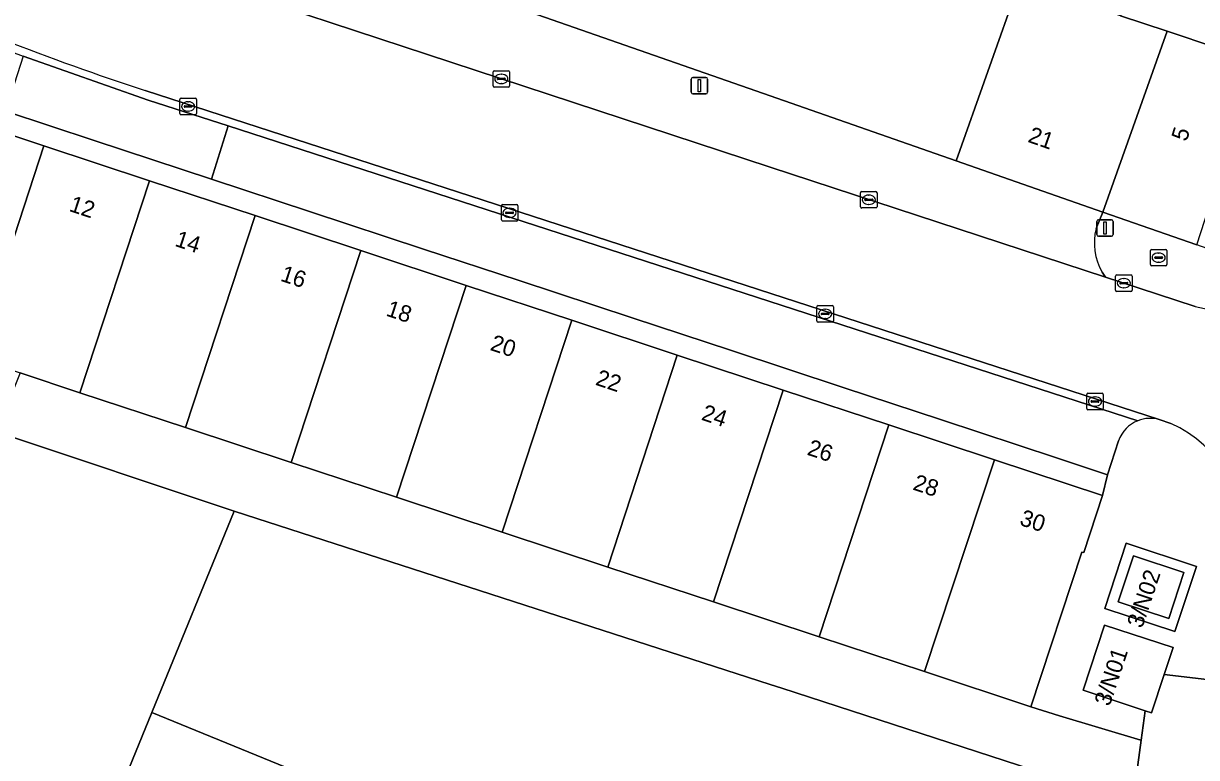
# Model space of a CAD drawing. Extents: x 160554 to 161248, y 385329 to 386506.
# Drawn here: x 160954.7 to 161025.9, y 385787.9 to 385832.5 of the extents above; entities that cross this region are included whole.
import ezdxf

# ---------------------------------------------------------------- set-up
doc = ezdxf.new("R2010")
doc.units = 0
for name, color, linetype in [('IMGEO_Brandkraan', 7, 'Continuous'), ('IMGEO_Erf', 7, 'Continuous'), ('IMGEO_Kolk', 7, 'Continuous'), ('IMGEO_Lichtmast', 7, 'Continuous'), ('IMGEO_Pand', 7, 'Continuous'), ('IMGEO_Pand_nummerreeks', 7, 'Continuous'), ('IMGEO_Parkeervlak_open', 7, 'Continuous'), ('IMGEO_Rijbaan_lokaal_gesloten', 7, 'Continuous'), ('IMGEO_Rijbaan_lokaal_open', 7, 'Continuous'), ('IMGEO_Voetpad_open', 7, 'Continuous')]:
    doc.layers.add(name, color=color, linetype=linetype)

msp = doc.modelspace()

# ---------------------------------------------------------------- linework, layer by layer
at = {"layer": 'IMGEO_Brandkraan'}
for p, q in [((161023.096, 385817.872), (161023.096, 385818.724)), ((161023.171, 385818.798), (161024.023, 385818.798)), ((161023.355, 385818.292), (161023.355, 385818.304)), ((161023.398, 385818.341), (161023.796, 385818.341)), ((161023.584, 385818.578), (161023.609, 385818.578)), ((161023.839, 385818.304), (161023.839, 385818.292)), ((161024.097, 385818.724), (161024.097, 385817.872)), ((161024.023, 385817.798), (161023.171, 385817.798)), ((161023.793, 385818.255), (161023.395, 385818.255)), ((161023.607, 385818.018), (161023.582, 385818.018))]:
    msp.add_line(p, q, dxfattribs=at)
for points in [[(161023.096, 385817.872), (161023.096, 385818.724)], [(161023.171, 385818.798), (161024.023, 385818.798)], [(161024.097, 385818.724), (161024.097, 385817.872)], [(161024.023, 385817.798), (161023.171, 385817.798)]]:
    msp.add_lwpolyline(points, dxfattribs=at)
for centre, radius, start, end in [((161023.173, 385818.722), 0.0765, 91.55205, 178.44795), ((161023.173, 385818.722), 0.0765, 91.55205, 178.44795), ((161023.395, 385818.301), 0.0403, 85.87752, 175.75265), ((161023.392, 385818.291), 0.0366, 178.93798, 274.71019), ((161023.796, 385818.298), 0.043, 264.86636, 352.45326), ((161023.8, 385818.303), 0.0386, 1.73085, 96.63898), ((161024.021, 385818.722), 0.0765, 1.55205, 88.44795), ((161024.021, 385818.722), 0.0765, 1.55205, 88.44795), ((161023.173, 385817.874), 0.0765, 181.55205, 268.44795), ((161023.173, 385817.874), 0.0765, 181.55205, 268.44795), ((161024.021, 385817.874), 0.0765, 271.55205, 358.44795), ((161024.021, 385817.874), 0.0765, 271.55205, 358.44795)]:
    msp.add_arc(centre, radius, start, end, dxfattribs=at)
for centre, major_axis, ratio, start_param, end_param in [((161023.583, 385818.298), (-0.387, 0.002), 0.722429, 4.712389, 7.853982), ((161023.608, 385818.298), (-0.39, 0.002), 0.717154, 1.570796, 4.712389)]:
    msp.add_ellipse(centre, major_axis=major_axis, ratio=ratio, start_param=start_param, end_param=end_param, dxfattribs=at)
at = {"layer": 'IMGEO_Erf'}
msp.add_lwpolyline([(161000.723, 385792.149), (161000, 385792.384), (160967.473, 385802.912), (160962.472, 385790.676), (160994.492, 385777.59), (160990.901, 385768.804), (160991.347, 385768.622), (161000, 385765.086), (161004.935, 385763.068), (161009.112, 385773.288), (161020.238, 385768.73), (161021.018, 385775.893), (161021.509, 385780.411), (161021.746, 385782.591), (161022.037, 385785.258), (161015.078, 385787.473)], close=True, dxfattribs=at)
at = {"layer": 'IMGEO_Kolk'}
for p, q in [((160983.185, 385828.725), (160983.185, 385829.577)), ((160983.26, 385829.651), (160984.112, 385829.651)), ((160983.444, 385829.145), (160983.444, 385829.157)), ((160983.882, 385829.108), (160983.484, 385829.108)), ((160983.487, 385829.194), (160983.885, 385829.194)), ((160983.673, 385829.431), (160983.698, 385829.431)), ((160983.928, 385829.157), (160983.928, 385829.145)), ((160984.186, 385829.577), (160984.186, 385828.725)), ((160984.112, 385828.651), (160983.26, 385828.651)), ((160983.696, 385828.871), (160983.671, 385828.871)), ((160964.171, 385827.054), (160964.171, 385827.906)), ((160964.246, 385827.98), (160965.098, 385827.98)), ((160964.659, 385827.76), (160964.684, 385827.76)), ((160965.172, 385827.906), (160965.172, 385827.054)), ((160965.098, 385826.98), (160964.246, 385826.98)), ((160964.43, 385827.474), (160964.43, 385827.486)), ((160964.868, 385827.437), (160964.47, 385827.437)), ((160964.473, 385827.523), (160964.871, 385827.523)), ((160964.682, 385827.2), (160964.657, 385827.2)), ((160964.914, 385827.486), (160964.914, 385827.474)), ((161005.496, 385821.387), (161005.496, 385822.239)), ((161005.571, 385822.313), (161006.423, 385822.313)), ((161005.798, 385821.856), (161006.196, 385821.856)), ((161005.984, 385822.093), (161006.009, 385822.093)), ((161006.497, 385822.239), (161006.497, 385821.387)), ((160983.688, 385820.596), (160983.688, 385821.448)), ((160983.763, 385821.522), (160984.615, 385821.522)), ((160984.176, 385821.302), (160984.201, 385821.302)), ((160984.689, 385821.448), (160984.689, 385820.596)), ((161006.423, 385821.313), (161005.571, 385821.313)), ((161005.755, 385821.807), (161005.755, 385821.819)), ((161006.193, 385821.77), (161005.795, 385821.77)), ((161006.007, 385821.533), (161005.982, 385821.533)), ((161006.239, 385821.819), (161006.239, 385821.807)), ((160984.615, 385820.522), (160983.763, 385820.522)), ((160983.947, 385821.016), (160983.947, 385821.028)), ((160984.385, 385820.979), (160983.987, 385820.979)), ((160983.99, 385821.065), (160984.388, 385821.065)), ((160984.199, 385820.742), (160984.174, 385820.742)), ((160984.431, 385821.028), (160984.431, 385821.016)), ((161020.982, 385816.32), (161020.982, 385817.172)), ((161021.057, 385817.246), (161021.909, 385817.246)), ((161021.47, 385817.026), (161021.495, 385817.026)), ((161021.983, 385817.172), (161021.983, 385816.32)), ((161021.909, 385816.246), (161021.057, 385816.246)), ((161021.241, 385816.74), (161021.241, 385816.752)), ((161021.679, 385816.703), (161021.281, 385816.703)), ((161021.284, 385816.789), (161021.682, 385816.789)), ((161021.493, 385816.466), (161021.468, 385816.466)), ((161021.725, 385816.752), (161021.725, 385816.74)), ((161002.85, 385814.457), (161002.85, 385815.309)), ((161002.925, 385815.383), (161003.777, 385815.383)), ((161003.109, 385814.877), (161003.109, 385814.889)), ((161003.547, 385814.84), (161003.149, 385814.84)), ((161003.152, 385814.926), (161003.55, 385814.926)), ((161003.338, 385815.163), (161003.363, 385815.163)), ((161003.593, 385814.889), (161003.593, 385814.877)), ((161003.851, 385815.309), (161003.851, 385814.457)), ((161003.777, 385814.383), (161002.925, 385814.383)), ((161003.361, 385814.603), (161003.336, 385814.603)), ((161019.23, 385809.139), (161019.23, 385809.991)), ((161019.305, 385810.065), (161020.157, 385810.065)), ((161019.718, 385809.845), (161019.743, 385809.845)), ((161020.231, 385809.991), (161020.231, 385809.139)), ((161020.157, 385809.065), (161019.305, 385809.065)), ((161019.489, 385809.559), (161019.489, 385809.571)), ((161019.927, 385809.522), (161019.529, 385809.522)), ((161019.532, 385809.608), (161019.93, 385809.608)), ((161019.741, 385809.285), (161019.716, 385809.285)), ((161019.973, 385809.571), (161019.973, 385809.559))]:
    msp.add_line(p, q, dxfattribs=at)
for points in [[(160983.185, 385828.725), (160983.185, 385829.577)], [(160983.26, 385829.651), (160984.112, 385829.651)], [(160984.186, 385829.577), (160984.186, 385828.725)], [(160984.112, 385828.651), (160983.26, 385828.651)], [(160964.171, 385827.054), (160964.171, 385827.906)], [(160964.246, 385827.98), (160965.098, 385827.98)], [(160965.172, 385827.906), (160965.172, 385827.054)], [(160965.098, 385826.98), (160964.246, 385826.98)], [(161005.496, 385821.387), (161005.496, 385822.239)], [(161005.571, 385822.313), (161006.423, 385822.313)], [(161006.497, 385822.239), (161006.497, 385821.387)], [(160983.688, 385820.596), (160983.688, 385821.448)], [(160983.763, 385821.522), (160984.615, 385821.522)], [(160984.689, 385821.448), (160984.689, 385820.596)], [(161006.423, 385821.313), (161005.571, 385821.313)], [(160984.615, 385820.522), (160983.763, 385820.522)], [(161020.982, 385816.32), (161020.982, 385817.172)], [(161021.057, 385817.246), (161021.909, 385817.246)], [(161021.983, 385817.172), (161021.983, 385816.32)], [(161021.909, 385816.246), (161021.057, 385816.246)], [(161002.85, 385814.457), (161002.85, 385815.309)], [(161002.925, 385815.383), (161003.777, 385815.383)], [(161003.851, 385815.309), (161003.851, 385814.457)], [(161003.777, 385814.383), (161002.925, 385814.383)], [(161019.23, 385809.139), (161019.23, 385809.991)], [(161019.305, 385810.065), (161020.157, 385810.065)], [(161020.231, 385809.991), (161020.231, 385809.139)], [(161020.157, 385809.065), (161019.305, 385809.065)]]:
    msp.add_lwpolyline(points, dxfattribs=at)
for centre, radius, start, end in [((160983.262, 385829.575), 0.0765, 91.55205, 178.44795), ((160983.262, 385829.575), 0.0765, 91.55205, 178.44795), ((160983.484, 385829.154), 0.0403, 85.87752, 175.75265), ((160983.481, 385829.144), 0.0366, 178.93798, 274.71019), ((160983.885, 385829.151), 0.043, 264.86636, 352.45326), ((160983.889, 385829.156), 0.0386, 1.73085, 96.63898), ((160984.11, 385829.575), 0.0765, 1.55205, 88.44795), ((160984.11, 385829.575), 0.0765, 1.55205, 88.44795), ((160983.262, 385828.727), 0.0765, 181.55205, 268.44795), ((160983.262, 385828.727), 0.0765, 181.55205, 268.44795), ((160984.11, 385828.727), 0.0765, 271.55205, 358.44795), ((160984.11, 385828.727), 0.0765, 271.55205, 358.44795), ((160964.248, 385827.904), 0.0765, 91.55205, 178.44795), ((160964.248, 385827.904), 0.0765, 91.55205, 178.44795), ((160965.096, 385827.904), 0.0765, 1.55205, 88.44795), ((160965.096, 385827.904), 0.0765, 1.55205, 88.44795), ((160964.248, 385827.056), 0.0765, 181.55205, 268.44795), ((160964.248, 385827.056), 0.0765, 181.55205, 268.44795), ((160964.47, 385827.483), 0.0403, 85.87752, 175.75265), ((160964.467, 385827.473), 0.0366, 178.93798, 274.71019), ((160964.871, 385827.48), 0.043, 264.86636, 352.45326), ((160964.875, 385827.485), 0.0386, 1.73085, 96.63898), ((160965.096, 385827.056), 0.0765, 271.55205, 358.44795), ((160965.096, 385827.056), 0.0765, 271.55205, 358.44795), ((161005.573, 385822.237), 0.0765, 91.55205, 178.44795), ((161005.573, 385822.237), 0.0765, 91.55205, 178.44795), ((161005.795, 385821.816), 0.0403, 85.87752, 175.75265), ((161006.2, 385821.818), 0.0386, 1.73085, 96.63898), ((161006.421, 385822.237), 0.0765, 1.55205, 88.44795), ((161006.421, 385822.237), 0.0765, 1.55205, 88.44795), ((160983.765, 385821.446), 0.0765, 91.55205, 178.44795), ((160983.765, 385821.446), 0.0765, 91.55205, 178.44795), ((160984.613, 385821.446), 0.0765, 1.55205, 88.44795), ((160984.613, 385821.446), 0.0765, 1.55205, 88.44795), ((161005.573, 385821.389), 0.0765, 181.55205, 268.44795), ((161005.573, 385821.389), 0.0765, 181.55205, 268.44795), ((161005.792, 385821.806), 0.0366, 178.93798, 274.71019), ((161006.196, 385821.813), 0.043, 264.86636, 352.45326), ((161006.421, 385821.389), 0.0765, 271.55205, 358.44795), ((161006.421, 385821.389), 0.0765, 271.55205, 358.44795), ((160983.765, 385820.598), 0.0765, 181.55205, 268.44795), ((160983.765, 385820.598), 0.0765, 181.55205, 268.44795), ((160983.987, 385821.025), 0.0403, 85.87752, 175.75265), ((160983.984, 385821.015), 0.0366, 178.93798, 274.71019), ((160984.388, 385821.022), 0.043, 264.86636, 352.45326), ((160984.392, 385821.027), 0.0386, 1.73085, 96.63898), ((160984.613, 385820.598), 0.0765, 271.55205, 358.44795), ((160984.613, 385820.598), 0.0765, 271.55205, 358.44795), ((161021.059, 385817.17), 0.0765, 91.55205, 178.44795), ((161021.059, 385817.17), 0.0765, 91.55205, 178.44795), ((161021.907, 385817.17), 0.0765, 1.55205, 88.44795), ((161021.907, 385817.17), 0.0765, 1.55205, 88.44795), ((161021.059, 385816.322), 0.0765, 181.55205, 268.44795), ((161021.059, 385816.322), 0.0765, 181.55205, 268.44795), ((161021.281, 385816.749), 0.0403, 85.87752, 175.75265), ((161021.278, 385816.739), 0.0366, 178.93798, 274.71019), ((161021.682, 385816.746), 0.043, 264.86636, 352.45326), ((161021.686, 385816.751), 0.0386, 1.73085, 96.63898), ((161021.907, 385816.322), 0.0765, 271.55205, 358.44795), ((161021.907, 385816.322), 0.0765, 271.55205, 358.44795), ((161002.927, 385815.307), 0.0765, 91.55205, 178.44795), ((161002.927, 385815.307), 0.0765, 91.55205, 178.44795), ((161003.149, 385814.886), 0.0403, 85.87752, 175.75265), ((161003.146, 385814.876), 0.0366, 178.93798, 274.71019), ((161003.55, 385814.883), 0.043, 264.86636, 352.45326), ((161003.554, 385814.888), 0.0386, 1.73085, 96.63898), ((161003.775, 385815.307), 0.0765, 1.55205, 88.44795), ((161003.775, 385815.307), 0.0765, 1.55205, 88.44795), ((161002.927, 385814.459), 0.0765, 181.55205, 268.44795), ((161002.927, 385814.459), 0.0765, 181.55205, 268.44795), ((161003.775, 385814.459), 0.0765, 271.55205, 358.44795), ((161003.775, 385814.459), 0.0765, 271.55205, 358.44795), ((161019.307, 385809.989), 0.0765, 91.55205, 178.44795), ((161019.307, 385809.989), 0.0765, 91.55205, 178.44795), ((161020.155, 385809.989), 0.0765, 1.55205, 88.44795), ((161020.155, 385809.989), 0.0765, 1.55205, 88.44795), ((161019.307, 385809.141), 0.0765, 181.55205, 268.44795), ((161019.307, 385809.141), 0.0765, 181.55205, 268.44795), ((161019.529, 385809.568), 0.0403, 85.87752, 175.75265), ((161019.526, 385809.558), 0.0366, 178.93798, 274.71019), ((161019.93, 385809.565), 0.043, 264.86636, 352.45326), ((161019.934, 385809.57), 0.0386, 1.73085, 96.63898), ((161020.155, 385809.141), 0.0765, 271.55205, 358.44795), ((161020.155, 385809.141), 0.0765, 271.55205, 358.44795)]:
    msp.add_arc(centre, radius, start, end, dxfattribs=at)
for centre, major_axis, ratio, start_param, end_param in [((160983.672, 385829.151), (-0.387, 0.002), 0.722429, 4.712389, 7.853982), ((160983.697, 385829.151), (-0.39, 0.002), 0.717154, 1.570796, 4.712389), ((160964.658, 385827.48), (-0.387, 0.002), 0.722429, 4.712389, 7.853982), ((160964.683, 385827.48), (-0.39, 0.002), 0.717154, 1.570796, 4.712389), ((161005.983, 385821.813), (-0.387, 0.002), 0.722429, 4.712389, 7.853982), ((161006.008, 385821.813), (-0.39, 0.002), 0.717154, 1.570796, 4.712389), ((160984.175, 385821.022), (-0.387, 0.002), 0.722429, 4.712389, 7.853982), ((160984.2, 385821.022), (-0.39, 0.002), 0.717154, 1.570796, 4.712389), ((161021.469, 385816.746), (-0.387, 0.002), 0.722429, 4.712389, 7.853982), ((161021.494, 385816.746), (-0.39, 0.002), 0.717154, 1.570796, 4.712389), ((161003.337, 385814.883), (-0.387, 0.002), 0.722429, 4.712389, 7.853982), ((161003.362, 385814.883), (-0.39, 0.002), 0.717154, 1.570796, 4.712389), ((161019.717, 385809.565), (-0.387, 0.002), 0.722429, 4.712389, 7.853982), ((161019.742, 385809.565), (-0.39, 0.002), 0.717154, 1.570796, 4.712389)]:
    msp.add_ellipse(centre, major_axis=major_axis, ratio=ratio, start_param=start_param, end_param=end_param, dxfattribs=at)
at = {"layer": 'IMGEO_Lichtmast'}
for p, q in [((160995.216, 385828.337), (160995.216, 385829.137)), ((160995.216, 385829.137), (160995.216, 385828.337)), ((160995.316, 385829.237), (160996.106, 385829.237)), ((160996.106, 385829.237), (160995.316, 385829.237)), ((160996.206, 385829.137), (160996.206, 385828.337)), ((160996.206, 385828.337), (160996.206, 385829.137)), ((160996.106, 385828.237), (160995.316, 385828.237)), ((160995.316, 385828.237), (160996.106, 385828.237)), ((161019.84, 385819.7), (161019.84, 385820.5)), ((161019.84, 385820.5), (161019.84, 385819.7)), ((161019.94, 385820.6), (161020.73, 385820.6)), ((161020.73, 385820.6), (161019.94, 385820.6)), ((161020.83, 385820.5), (161020.83, 385819.7)), ((161020.83, 385819.7), (161020.83, 385820.5)), ((161020.73, 385819.6), (161019.94, 385819.6)), ((161019.94, 385819.6), (161020.73, 385819.6))]:
    msp.add_line(p, q, dxfattribs=at)
for points in [[(160995.636, 385829.112), (160995.786, 385829.112), (160995.786, 385828.362), (160995.636, 385828.362), (160995.636, 385829.112)], [(161020.26, 385820.475), (161020.41, 385820.475), (161020.41, 385819.725), (161020.26, 385819.725), (161020.26, 385820.475)]]:
    msp.add_lwpolyline(points, dxfattribs=at)
for centre, start, end in [((160995.316, 385829.137), 90, 180), ((160995.316, 385829.137), 90, 180), ((160996.106, 385829.137), 0, 90), ((160996.106, 385829.137), 360, 90), ((160995.316, 385828.337), 180, 270), ((160995.316, 385828.337), 180, 270), ((160996.106, 385828.337), 270, 0), ((160996.106, 385828.337), 270, 0), ((161019.94, 385820.5), 90, 180), ((161019.94, 385820.5), 90, 180), ((161020.73, 385820.5), 0, 90), ((161020.73, 385820.5), 360, 90), ((161019.94, 385819.7), 180, 270), ((161019.94, 385819.7), 180, 270), ((161020.73, 385819.7), 270, 0), ((161020.73, 385819.7), 270, 0)]:
    msp.add_arc(centre, 0.1, start, end, dxfattribs=at)
at = {"layer": 'IMGEO_Pand'}
for points in [[(160944.538, 385862.952), (160944.826, 385863.775), (160944.877, 385863.921), (160939.825, 385865.879), (160939.428, 385864.745), (160937.341, 385865.474), (160935.807, 385861.085), (160935.65, 385860.635), (160934.169, 385856.4), (160932.519, 385851.68), (160932.947, 385851.53), (161000, 385828.117), (161011.302, 385824.17), (161015.15, 385835.043), (161016.153, 385837.917), (161000, 385843.564)], [(161028.571, 385835.139), (161022.748, 385837.175), (161021.286, 385832.99), (161024.105, 385832.047), (161027.138, 385831.032)], [(161020.216, 385821.058), (161024.105, 385832.047), (161021.286, 385832.99), (161015.15, 385835.043), (161011.302, 385824.17)], [(161025.905, 385819.071), (161028.066, 385825.689), (161029.548, 385830.225), (161027.138, 385831.032), (161024.105, 385832.047), (161020.216, 385821.058)], [(160955.918, 385825.083), (160949.248, 385827.289), (160945.011, 385814.496), (160951.691, 385812.236)], [(160951.691, 385812.236), (160954.47, 385811.296), (160958.1, 385810.097), (160962.325, 385822.967), (160955.918, 385825.083)], [(160968.736, 385820.849), (160962.325, 385822.967), (160958.1, 385810.097), (160964.504, 385807.982)], [(160964.504, 385807.982), (160970.917, 385805.864), (160975.148, 385818.731), (160968.736, 385820.849)], [(160970.917, 385805.864), (160977.324, 385803.748), (160981.554, 385816.616), (160975.148, 385818.731)], [(160987.964, 385814.499), (160981.554, 385816.616), (160977.324, 385803.748), (160983.732, 385801.632)], [(160983.732, 385801.632), (160990.148, 385799.513), (160994.368, 385812.384), (160987.964, 385814.499)], [(161000.803, 385810.259), (160994.368, 385812.384), (160990.148, 385799.513), (160996.561, 385797.395)], [(160996.561, 385797.395), (161002.975, 385795.277), (161007.217, 385808.14), (161000.803, 385810.259)], [(160962.472, 385790.676), (160967.473, 385802.912), (160953.012, 385807.728), (160949.553, 385799.263), (160931.297, 385754.531), (160932.023, 385754.224), (160932.167, 385754.781), (160932.365, 385755.361), (160941.389, 385751.626), (160946.183, 385753.169), (160946.649, 385752.951), (160945.566, 385750), (160945.353, 385749.419), (160944.823, 385749.599), (160944.596, 385749.072), (160945.129, 385748.857), (160945.33, 385748.776), (160945.831, 385750)], [(161013.631, 385806.022), (161007.217, 385808.14), (161002.975, 385795.277), (161009.389, 385793.158)], [(161020.182, 385803.858), (161013.631, 385806.022), (161009.389, 385793.158), (161015.834, 385791.03), (161018.94, 385800.419), (161019.044, 385800.392)], [(161025.133, 385799.18), (161022.062, 385800.193), (161021.141, 385797.399), (161024.212, 385796.387)], [(161023.931, 385792.984), (161024.47, 385794.616), (161020.314, 385795.986), (161019.011, 385792.034), (161022.786, 385790.789), (161023.166, 385790.664)], [(160948.328, 385747.565), (160959.223, 385743.167), (160965.928, 385740.46), (160976.007, 385736.39), (160977.537, 385735.773), (160977.766, 385735.68), (160983.669, 385750), (160991.347, 385768.622), (160990.901, 385768.804), (160994.492, 385777.59), (160962.472, 385790.676), (160945.831, 385750), (160945.33, 385748.776)]]:
    msp.add_lwpolyline(points, close=True, dxfattribs=at)
at = {"layer": 'IMGEO_Parkeervlak_open'}
for points in [[(161019.795, 385820.06), (161020.216, 385821.058), (161011.302, 385824.17), (161000, 385828.117), (160932.947, 385851.53)], [(160963.127, 385835.929), (160982.091, 385829.674), (161000, 385823.784), (161020.378, 385817.108), (161020.16, 385817.413)], [(161028.597, 385818.115), (161025.905, 385819.071), (161020.216, 385821.058), (161019.795, 385820.06)], [(161020.16, 385817.413), (161020.378, 385817.108), (161021.308, 385816.803), (161025.817, 385815.326)]]:
    msp.add_lwpolyline(points, dxfattribs=at)
for centre, radius, start, end in [((161023.343, 385819.201), 3.651, 166.385, 209.31723), ((161023.343, 385819.201), 3.651, 166.385, 209.31723), ((161027.278, 385821.286), 6.136, 256.22773, 340.1079)]:
    msp.add_arc(centre, radius, start, end, dxfattribs=at)
at = {"layer": 'IMGEO_Rijbaan_lokaal_gesloten'}
for points in [[(161021.308, 385816.803), (161020.378, 385817.108), (161000, 385823.784), (160982.091, 385829.674), (160963.127, 385835.929)], [(160962.067, 385828.449), (161023.625, 385808.465), (161024.336, 385808.234)], [(161025.817, 385815.326), (161021.308, 385816.803)]]:
    msp.add_lwpolyline(points, dxfattribs=at)
for centre, radius, start, end in [((161011.773, 385980.572), 160.038, 248.60785, 251.90538), ((161027.278, 385821.286), 6.136, 256.22773, 340.1079), ((161021.231, 385801.325), 7.574, 353.66767, 65.79818)]:
    msp.add_arc(centre, radius, start, end, dxfattribs=at)
at = {"layer": 'IMGEO_Rijbaan_lokaal_open'}
for points in [[(160953.399, 385831.56), (160943.719, 385835.176), (160936.154, 385838.328), (160900.444, 385853.054), (160893.378, 385856.039), (160893.195, 385855.607), (160893.326, 385855.547), (160893.484, 385855.474), (160893.513, 385855.461), (160893.952, 385855.26), (160943.83, 385834.567), (160947.696, 385833.124), (160950.55, 385832.059), (160954.657, 385830.526), (160962.252, 385827.866), (160967.092, 385826.298), (161022.331, 385808.398)], [(161023.625, 385808.465), (160962.067, 385828.449)]]:
    msp.add_lwpolyline(points, dxfattribs=at)
for centre, radius, start, end in [((161011.773, 385980.572), 160.038, 248.60785, 251.90538), ((161023.077, 385806.52), 2.021, 74.26485, 111.66312)]:
    msp.add_arc(centre, radius, start, end, dxfattribs=at)
at = {"layer": 'IMGEO_Voetpad_open'}
for points in [[(160962.252, 385827.866), (160954.657, 385830.526), (160953.585, 385827.196), (160958.971, 385825.42), (160966.095, 385823.068), (160967.092, 385826.298)], [(161009.389, 385793.158), (161002.975, 385795.277), (160996.561, 385797.395), (160990.148, 385799.513), (160983.732, 385801.632), (160977.324, 385803.748), (160970.917, 385805.864), (160964.504, 385807.982), (160958.1, 385810.097), (160954.47, 385811.296), (160953.012, 385807.728), (160967.473, 385802.912), (161000, 385792.384), (161000.723, 385792.149), (161015.078, 385787.473), (161022.037, 385785.258), (161022.544, 385789.002), (161022.519, 385789.006), (161017.577, 385790.485), (161015.834, 385791.03)], [(161025.889, 385799.552), (161021.626, 385800.957), (161020.322, 385797), (161024.583, 385795.594)], [(161024.583, 385795.594), (161020.322, 385797), (161021.626, 385800.957), (161025.889, 385799.552)], [(161024.212, 385796.387), (161021.141, 385797.399), (161022.062, 385800.193), (161025.133, 385799.18)]]:
    msp.add_lwpolyline(points, close=True, dxfattribs=at)
for points in [[(160949.248, 385827.289), (160955.918, 385825.083), (160962.325, 385822.967), (160968.736, 385820.849), (160975.148, 385818.731), (160981.554, 385816.616), (160987.964, 385814.499), (160994.368, 385812.384), (161000.803, 385810.259), (161007.217, 385808.14), (161013.631, 385806.022), (161020.182, 385803.858), (161020.495, 385805.112), (161017.392, 385806.137), (161010.411, 385808.441), (161004.445, 385810.41), (160997.653, 385812.653), (160991.634, 385814.639), (160984.766, 385816.906), (160978.962, 385818.822), (160972.108, 385821.084), (160966.095, 385823.068), (160958.971, 385825.42), (160953.585, 385827.196)], [(160967.092, 385826.298), (160966.095, 385823.068)], [(161022.331, 385808.398), (160967.092, 385826.298)], [(160966.095, 385823.068), (160972.108, 385821.084)], [(160972.108, 385821.084), (160978.962, 385818.822)], [(160978.962, 385818.822), (160984.766, 385816.906)], [(160984.766, 385816.906), (160991.634, 385814.639)], [(160991.634, 385814.639), (160997.653, 385812.653)], [(160997.653, 385812.653), (161004.445, 385810.41)], [(161004.445, 385810.41), (161010.411, 385808.441)], [(161010.411, 385808.441), (161017.392, 385806.137)], [(161024.336, 385808.234), (161023.625, 385808.465)], [(161021.167, 385807.181), (161020.495, 385805.112), (161020.182, 385803.858), (161019.044, 385800.392), (161018.94, 385800.419), (161015.834, 385791.03), (161017.577, 385790.485), (161022.519, 385789.006), (161022.544, 385789.002), (161022.786, 385790.789), (161019.011, 385792.034), (161020.314, 385795.986), (161024.47, 385794.616), (161023.931, 385792.984), (161027.908, 385792.526), (161028.163, 385795.052), (161028.759, 385800.49)], [(161020.495, 385805.112), (161021.167, 385807.181)], [(161017.392, 385806.137), (161020.495, 385805.112)], [(161027.908, 385792.526), (161023.931, 385792.984), (161023.166, 385790.664), (161022.786, 385790.789), (161022.544, 385789.002), (161022.037, 385785.258), (161021.746, 385782.591), (161026.321, 385782.026)]]:
    msp.add_lwpolyline(points, dxfattribs=at)
for centre, radius, start, end in [((161023.078, 385806.518), 2.023, 111.6802, 160.87013), ((161023.078, 385806.518), 2.023, 111.6802, 160.87013), ((161023.077, 385806.52), 2.021, 74.26485, 111.66312), ((161021.231, 385801.325), 7.574, 353.66767, 65.79818)]:
    msp.add_arc(centre, radius, start, end, dxfattribs=at)

# ---------------------------------------------------------------- texts
at = {"layer": 'IMGEO_Pand_nummerreeks'}
for s, rotation, p in [('21', 340.7552, (161015.604, 385825.337)), ('5', 71.91323, (161025.29, 385825.306)), ('12', 341.72327, (160957.392, 385821.142)), ('14', 341.72327, (160963.807, 385819.023)), ('16', 341.72327, (160970.218, 385816.905)), ('18', 341.72327, (160976.63, 385814.788)), ('20', 341.72327, (160982.952, 385812.7)), ('22', 341.72327, (160989.349, 385810.587)), ('24', 341.72327, (160995.775, 385808.465)), ('26', 341.72327, (161002.199, 385806.343)), ('28', 341.72327, (161008.617, 385804.224)), ('30', 341.72327, (161015.099, 385802.083)), ('3/N02', 71.45606, (161022.593, 385795.75)), ('3/N01', 71.56505, (161020.616, 385791.011))]:
    msp.add_text(s, height=1, rotation=rotation, dxfattribs=at).set_placement(p)

doc.saveas('drawing.dxf')
